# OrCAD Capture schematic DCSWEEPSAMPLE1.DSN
size A
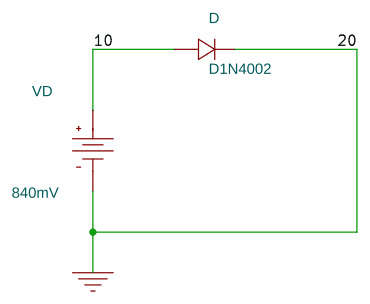
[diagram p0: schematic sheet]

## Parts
D  D1N4002  [DO-41]
VD  VDC

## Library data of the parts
D = D1N4002
VD = VDC: DC: 840mV

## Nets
0: D.2 VD.1(-)
10: D.1 VD.0(+)
